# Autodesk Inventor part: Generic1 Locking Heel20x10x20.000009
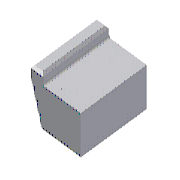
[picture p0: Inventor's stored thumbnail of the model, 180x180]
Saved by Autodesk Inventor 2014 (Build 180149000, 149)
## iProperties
Created: 2009-11
Part Number: Generic1 Locking Heel20x10x20.000009
Material: DIN 1.2162
Description: Locking Heel
Document SubType Name: Modeling
Designer: gaom
Standard Revision: 1
Manufacturer: Generic
Language: en-US
Size Designation: 20x10x20.000009
Categories: <MemberInstance><Categories><Category DisplayName="Mold" InternalName="349578f2-f4d4-4954-8c09-8e99297a61c0" Mnemonic="MOLD"><Category DisplayName="Slide Compon
Density: 7.85 g/cm^3
Appearance: Default
IsCustomPart: 1
Author: gaom
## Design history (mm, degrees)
sketch "Sketch1"
  geometry: L1 (20, 0)-(20, 4); L2 (20, 4)-(14, 4); L3 (14, 4)-(14, 0); L4 (14, 0)-(0, 0); L5 (0, 0)-(0, -10); L6 (0, -10)-(16.36, -10); L7 (16.36, -10)-(20, 0); 2 further points
  constraints: 14 end point, 4 parallel, 1 coincident, 1 horizontal alignment, 1 midpoint, 1 perpendicular, 1 vertical
  dimensions: "d0" = 6 distance between parallel lines of L1 L3 (= LH_l_); "d3" = 20 distance between parallel lines of L1 L5 (= LH_L); "d4" = 10 distance between parallel lines of L4 L6 (= LH_T); "d5" = 4 distance from line of L1.start L2 (= LH_H); "d6" = 20 deg angle of L1 L7 (= LH_ang - X_ang)
extrude "Extrusion1" new body sketch "Sketch1" stored distance "d7" = 38 (= LH_A); taper "d8" = 0 deg
node "LH_SL"
body "Solid1"
feature "Stitch Surface1" dims "d126" = 0.254 (derived)
sketch "Sketch2"
  geometry: L1 (-14, 0)-(0, 0) reference; L2 (0, 0)-(0, -10) reference; L3 (0, -10)-(-16.36, -10) reference; L4 (-16.36, -10)-(-20, 0) reference; L5 (-20, 5)-(-14, 5); L6 (-20, 4)-(-14, 4) reference; L7 (-20, 5)-(-20, 0); L8 (-14, 5)-(-14, 0)
  constraints: 6 end point, 1 parallel, 1 perpendicular
  dimensions: "d110" = 1 distance between parallel lines of L6 L5 (= LH_esh)
body "Srf1"
body "Srf2"
body "Srf3"
body "Srf4"
extrude_surface "ExtrusionSrf1" dims "d62" = 38 (= LH_A), "d63" = 0
patch "Boundary Patch1" dims "d77" = 0, "d111" = 0, "d112" = 0, "d113" = 0, "d114" = 0, "d115" = 0, "d116" = 0, "d117" = 0
patch "Boundary Patch2" dims "d118" = 0, "d119" = 0, "d120" = 0, "d121" = 0, "d122" = 0, "d123" = 0, "d124" = 0, "d125" = 0
other parameters: "LH_L" = 20 [user parameter; used in 1 equation term], "LH_T" = 10 [user parameter; used in 1 equation term], "LH_A" = 38 [user parameter; used in 2 equation terms], "LH_ang" = 20 deg [user parameter; used in 1 equation term], "LH_l_" = 6 [user parameter; used in 1 equation term], "LH_H" = 4 [user parameter; used in 1 equation term], "d95" = 0, "LH_esh" = 1 [user parameter; used in 1 equation term], "X_ang" = 0 deg [user parameter; used in 1 equation term]
